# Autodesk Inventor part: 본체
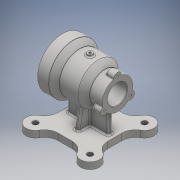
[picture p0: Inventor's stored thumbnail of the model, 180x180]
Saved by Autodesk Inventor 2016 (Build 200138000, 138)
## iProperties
Created: 2017-03
Part Number: 본체
Material: 일반
Document SubType Name: Modeling
Designer: USER
Density: 1 g/cm^3
Appearance: 기본값
Author: USER
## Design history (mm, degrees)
sketch "스케치1"
  geometry: L1 (0, 0)-(-100, 0); L2 (0, 35)-(0, 45); L3 (0, 45)-(-20, 45); L4 (-20, 45)-(-31, 36.63); L5 (-31, 36.63)-(-65, 36.63); L6 (-65, 36.63)-(-77, 27.5); L7 (-77, 27.5)-(-100, 27.5); L8 (0, 35)-(-20, 35); L9 (-23, 32)-(-23, 29); L10 (-26, 26)-(-67, 26); L11 (-70, 23)-(-70, 20.5); L12 (-73, 17.5)-(-100, 17.5); L13 (-100, 17.5)-(-100, 27.5); A1 r 3 centre (-20, 32) between (-20, 35) and (-23, 32); A2 r 3 centre (-67, 23) between (-67, 26) and (-70, 23); A3 r 3 centre (-26, 29) between (-26, 26) and (-23, 29); A4 r 3 centre (-73, 20.5) between (-73, 17.5) and (-70, 20.5); 5 further points
  constraints: 26 end point, 8 point on circle, 8 point on line, 8 tangent, 6 perpendicular, 4 centre point, 3 parallel, 2 equal radius, 1 horizontal, 1 midpoint, 1 vertical, 1 vertical alignment
  dimensions: "d0" = 100 distance between parallel lines of L13 L2; "d1" = 90 diameter of L3 L1; "d2" = 70 diameter of L8 L1; "d3" = 52 diameter of L10 L1; "d4" = 23 distance between parallel lines of L9 L2; "d5" = 47 distance between parallel lines of L11 L9; "d6" = 35 diameter of L12 L1; "d7" = 20 distance of L2.end L3.end; "d8" = 31 horizontal distance of L4.end L2.end; "d9" = 65 horizontal distance of L2.end L5.end; "d10" = 23 distance of L6.end L7.end; "d11" = 55 diameter of L7 L1; "d20" = 3 radius of A1; "d24" = 3 radius of A4
revolve "회전1" sketch "스케치1" stored, may be unused: angle "d12" = 90 deg
sketch "스케치2"
  geometry: L1 (0, 0)-(13.75, 23.816); L2 (0, 0)-(-27.5, 0); L3 (0, 0)-(13.75, -23.816); A1 r 7 centre (-27.5, 0) between (-26.609, 6.943) and (-26.609, -6.943); A2 r 7 centre (13.75, -23.816) between (7.292, -26.516) and (19.317, -19.573); A3 r 7 centre (13.75, 23.816) between (19.317, 19.573) and (7.292, 26.516); 2 further points
  constraints: 6 end point, 6 point on circle, 3 centre point, 1 horizontal, 1 horizontal alignment, 10 other
  dimensions: "d13" = 120 deg angle of L1 L2; "d14" = 120 deg angle of L2 L3; "d15" = 14 diameter of A1; "d16" = 14 diameter of A3; "d17" = 14 diameter of A2
extrude "돌출1" join sketch "스케치2" distance "d18" = 15; taper "d19" = 0 deg
fillet "모깎기1" dims "d21" = 3
fillet "모깎기2" dims "d22" = 1
fillet "모깎기3" dims "d23" = 1
node "작업 평면1"
sketch "스케치8"
  geometry: L1 (50, 0)-(99.497, 49.497); L2 (50, 0)-(120, 0); L3 (5, 45)-(95, 45); L4 (95, 45)-(95, -45); L5 (95, -45)-(5, -45); L6 (5, -45)-(5, 45); L7 (5, 0)-(95, 0); L8 (50, -45)-(50, 45); A1 r 70 centre (50, 0) between (99.497, 49.497) and (120, 0); 1 further point
  constraints: 16 end point, 5 midpoint, 2 horizontal, 2 horizontal alignment, 2 parallel, 2 point on circle, 1 centre point, 1 perpendicular
  dimensions: "d82" = 140 diameter of A1; "d83" = 50 distance of L1.start point (0, 0); "d84" = 45 deg angle of L2 L1; "d88" = 90 distance of L3.start L3.end; "d89" = 90 distance of L5.end L3.start
extrude "돌출3" join sketch "스케치8" distance "d90" = 12; taper "d91" = 0 deg
sketch "스케치9"
  geometry: L1 (5, -45)-(5, 45) reference; L2 (5, 0)-(95, 0); L3 (95, 45)-(95, -45) reference; L4 (95, -45)-(5, -45) reference; L5 (5, 45)-(95, 45) reference; L6 (50, 45)-(50, -45); L7 (50, 0)-(99.497, 49.497); A1 r 70 centre (50, 0) between (99.497, 49.497) and (110.143, 35.816); A2 r 17 centre (99.497, 49.497) between (107.796, 34.661) and (84.661, 57.796); A3 r 25 centre (120, 12.842) between (110.143, 35.816) and (95, 12.842); A4 r 25 centre (62.842, 70) between (62.842, 45) and (85.816, 60.143); 1 further point
  constraints: 11 point on circle, 6 end point, 5 midpoint, 4 centre point, 4 tangent, 2 point on line, 1 coincident
  dimensions: "d92" = 140 diameter of A1; "d93" = 45 deg angle of L2 L7; "d94" = 34 diameter of A2; "d97" = 50 diameter of A3; "d98" = 50 diameter of A4
extrude "돌출4" join sketch "스케치9" distance "d99" = 12; taper "d100" = 0 deg
sketch "스케치11"
  geometry: C1 r 5 at (50, 0); 1 further point
  constraints: 1 centre point, 1 horizontal alignment
  dimensions: "d112" = 10 diameter of C1; "d113" = 50 distance of C1.centre point (0, 0)
extrude "돌출5" cut sketch "스케치11" distance "d114" = 12; taper "d115" = 0 deg
sketch "스케치12"
  geometry: C1 r 5 at (50, 0); C2 r 5 at (50, 0) reference; 1 further point
  constraints: 1 centre point, 1 concentric
  dimensions: "d119" = 10 diameter of C1
extrude "돌출6" join sketch "스케치12" distance "d120" = 12; taper "d121" = 0 deg
sketch "스케치13"
  geometry: L1 (16.497, -70)-(16.497, -82) reference; L2 (-116.497, -70)-(-116.497, -82) reference; L3 (-13, -45)-(-13, -70); L4 (-87, -27.5)-(-87, -70); L5 (-84.661, -70)-(-62.842, -70) reference; L6 (-76.732, -27.704)-(-65, -36.63) reference; L7 (-37.158, -82)-(-62.842, -82) reference; L8 (-50, 46.891)-(-50, -110.432); L9 (-19.663, -45)-(0, -45) reference; L10 (-100, -19.881)-(-88, -19.881) reference; L11 (-100, -19.881)-(-100, -19.881) reference; L12 (-88, -19.881)-(-100, -19.881) reference; L13 (-84, -10.332)-(-84, -16.905) reference; L14 (-100, -6.513)-(-88, -6.513) reference; L15 (-100, -6.513)-(-100, 26.395) reference; L16 (-88, 26.395)-(-100, 26.395) reference; L17 (-84, 27.237)-(-84, 27.237) reference; L18 (-100, 26.395)-(-88, 26.395) reference; L19 (-100, 26.395)-(-100, -6.513) reference; L20 (-88, -6.513)-(-100, -6.513) reference; L21 (-84, -16.905)-(-84, -10.332) reference; L22 (-77.337, -27.5)-(-77.337, 27.5) reference; L23 (-100, -27.5)-(-77.337, -27.5) reference; L24 (-13, -70)-(-87, -70); L25 (16.497, -70)-(-15.339, -70) reference; L26 (-20.268, -44.796)-(-20.268, 44.796) reference; L27 (-13, -45)-(-20.268, -44.796); L28 (-30.732, 36.835)-(-30.732, -36.835) reference; L29 (-20.268, -44.796)-(-30.732, -36.835); L30 (-30.732, -36.835)-(-20.268, -44.796) reference; L31 (-30.732, -36.835)-(-77.337, -27.5); 2 further points
  constraints: 14 end point, 3 point on line, 3 vertical, 2 collinear, 6 other
  dimensions: "d122" = 50 distance from line of point (0, 0) L8; "d123" = 37 distance between parallel lines of L3 L8; "d124" = 37 distance between parallel lines of L4 L8
extrude "돌출7" join sketch "스케치13" stored distance "d125" = 8; taper "d126" = 0 deg
node "작업 평면2"
sketch "스케치14"
  geometry: L1 (-25, -70)-(-19.784, -40.418); L2 (25, -70)-(19.784, -40.418); L3 (0, 0)-(0, -82); L4 (-12.842, -82)-(12.842, -82) reference; L5 (-34.661, -70)-(-66.497, -70) reference; L6 (-34.661, -70)-(-12.842, -70) reference; L7 (12.842, -70)-(34.661, -70) reference; A1 r 45 centre (0, 0) between (-19.784, -40.418) and (19.784, -40.418) reference; 2 further points
  constraints: 6 end point, 2 point on circle, 2 point on line, 1 midpoint
  dimensions: "d129" = 100 deg angle of L5 L1; "d130" = 25 distance from line of L3 L1.start; "d131" = 100 deg angle of L7 L2; "d132" = 25 distance from line of L2.start L3
feature "리브1" dims "d133" = 1, "d134" = 8, "d135" = 0, "d136" = 0, "d137" = 1, "d138" = 1
feature "리브2" dims "d139" = 1, "d140" = 8, "d141" = 0, "d142" = 0, "d143" = 1, "d144" = 1
fillet "모깎기4" dims "d145" = 3
sketch "스케치15" dims "d146" = 80
  geometry: 8 further points
  constraints: 2 horizontal alignment, 1 coincident, 9 other
  dimensions: "d149" = 360 deg dimension on point (0, 0) point (40, 0) (derived)
hole "구멍1" sketch "스케치15" at (40, 0), (20, 34.641), (-20, 34.641), (-40, 0), (-20, -34.641), (20, -34.641) diameter "d151" = 3.242; stored, may be unused: countersink angle "d155" = 90 deg, drill point angle "d157" = 118 deg; dims "d152" = 9, "d153" = 4, "d154" = 2, "d156" = 11
sketch "스케치16"
  geometry: C1 r 5 at (99.497, 49.497); C2 r 5 at (99.497, -49.497); C3 r 5 at (0.503, -49.497); C4 r 5 at (0.503, 49.497); A1 r 17 centre (99.497, 49.497) between (107.796, 34.661) and (84.661, 57.796) reference; A2 r 17 centre (99.497, -49.497) between (84.661, -57.796) and (107.796, -34.661) reference; A3 r 17 centre (0.503, -49.497) between (-7.796, -34.661) and (15.339, -57.796) reference; A4 r 17 centre (0.503, 49.497) between (15.339, 57.796) and (-7.796, 34.661) reference; 1 further point
  constraints: 4 centre point, 4 concentric
  dimensions: "d158" = 10 diameter of C1; "d159" = 10 diameter of C2; "d160" = 10 diameter of C4; "d161" = 10 diameter of C3
extrude "돌출8" cut sketch "스케치16" stored distance "d162" = 8; taper "d163" = 0 deg
sketch "스케치17"
  geometry: 4 further points
  constraints: 1 horizontal alignment, 4 other
  dimensions: "d164" = 27.5 distance of point (27.5, 0) point (0, 0); "d167" = 360 deg dimension on point (27.5, 0) point (0, 0) (derived)
hole "구멍2" sketch "스케치17" at (0, 0), (41.25, -23.816), (41.25, 23.816) diameter "d169" = 3.242; stored, may be unused: countersink angle "d173" = 90 deg, drill point angle "d175" = 118 deg; dims "d170" = 9, "d171" = 4, "d172" = 2, "d174" = 11
node "작업 평면3"
sketch "스케치18"
  geometry: C1 r 5 at (50, 0); 1 further point
  constraints: 1 centre point, 1 horizontal alignment
  dimensions: "d177" = 10 diameter of C1; "d178" = 50 distance of C1.centre point (0, 0)
extrude "돌출9" join sketch "스케치18" distance "d179" = 14; taper "d180" = 0 deg
fillet "모깎기5" dims "d181" = 3
sketch "스케치19"
  geometry: C1 r 5 at (0, 0) reference; 2 further points
  constraints: 1 coincident
hole "구멍3" sketch "스케치19" at (0, 0) diameter "d182" = 4.134; stored, may be unused: countersink angle "d186" = 90 deg, drill point angle "d188" = 118 deg; dims "d183" = 10, "d184" = 4, "d185" = 2, "d187" = 14.2
node "솔리드1"
pattern_circular "원형 패턴1" dims angle "d117" = 360 deg
node "투영된 루프1"
other parameters: "d25" = -82, "d79" = 34, "d176" = 26
